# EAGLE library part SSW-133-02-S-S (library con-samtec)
THROUGH-HOLE .025" SQ POST SOCKET Source: Samtec SSW.pdf
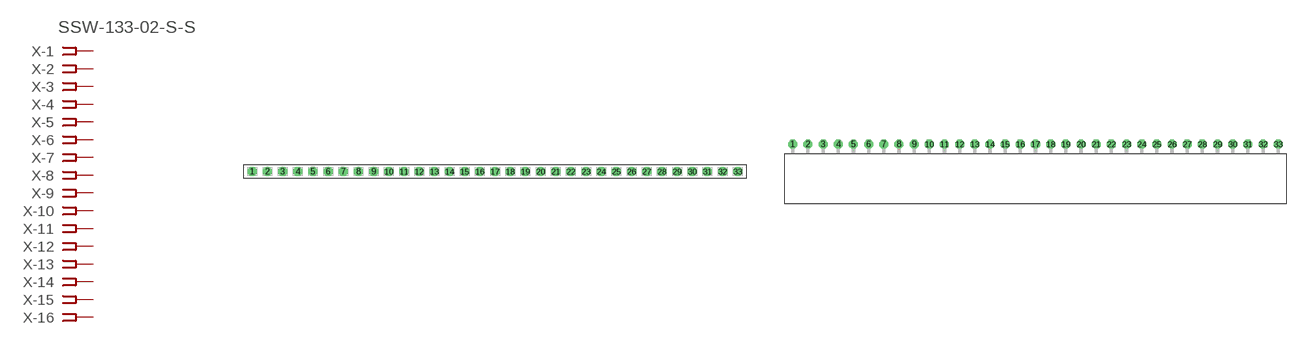
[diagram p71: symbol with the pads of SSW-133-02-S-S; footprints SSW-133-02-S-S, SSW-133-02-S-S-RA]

Designator prefix X; gates -1=FPINV -2=FPIN -3=FPIN -4=FPIN -5=FPIN -6=FPIN -7=FPIN -8=FPIN -9=FPIN -10=FPIN -11=FPIN -12=FPIN -13=FPIN -14=FPIN -15=FPIN -16=FPIN -17=FPIN -18=FPIN -19=FPIN -20=FPIN -21=FPIN -22=FPIN -23=FPIN -24=FPIN -25=FPIN -26=FPIN -27=FPIN -28=FPIN -29=FPIN -30=FPIN -31=FPIN -32=FPIN -33=FPIN

## SSW-133-02-S-S (MPN: SSW-133-02-S-S; OC_FARNELL: unknown; OC_NEWARK: 11P9855)  [SSW-133-02-S-S]
1  -1:1  pas
2  -2:1  pas
3  -3:1  pas
4  -4:1  pas
5  -5:1  pas
6  -6:1  pas
7  -7:1  pas
8  -8:1  pas
9  -9:1  pas
10  -10:1  pas
11  -11:1  pas
12  -12:1  pas
13  -13:1  pas
14  -14:1  pas
15  -15:1  pas
16  -16:1  pas
17  -17:1  pas
18  -18:1  pas
19  -19:1  pas
20  -20:1  pas
21  -21:1  pas
22  -22:1  pas
23  -23:1  pas
24  -24:1  pas
25  -25:1  pas
26  -26:1  pas
27  -27:1  pas
28  -28:1  pas
29  -29:1  pas
30  -30:1  pas
31  -31:1  pas
32  -32:1  pas
33  -33:1  pas

## SSW-133-02-S-S-RA (OC_FARNELL: unknown; OC_NEWARK: unknown)  [SSW-133-02-S-S-RA]
Pads as for SSW-133-02-S-S

## Footprint SSW-133-02-S-S (pad centres in mm)
THROUGH-HOLE .025" SQ POST SOCKET Source: Samtec SSW.pdf
drill 1 pad 1.5 octagon: 1 -40.64,0; 2 -38.1,0; 3 -35.56,0; 4 -33.02,0; 5 -30.48,0; 6 -27.94,0; 7 -25.4,0; 8 -22.86,0; 9 -20.32,0; 10 -17.78,0; 11 -15.24,0; 12 -12.7,0; 13 -10.16,0; 14 -7.62,0; 15 -5.08,0; 16 -2.54,0; 17 0,0; 18 2.54,0; 19 5.08,0; 20 7.62,0; 21 10.16,0; 22 12.7,0; 23 15.24,0; 24 17.78,0; 25 20.32,0; 26 22.86,0; 27 25.4,0; 28 27.94,0; 29 30.48,0; 30 33.02,0; 31 35.56,0; 32 38.1,0; 33 40.64,0

## Footprint SSW-133-02-S-S-RA (pad centres in mm)
THROUGH-HOLE .025" SQ POST SOCKET Source: Samtec SSW.pdf
drill 1 pad 1.5 octagon: 1 -40.64,1.524; 2 -38.1,1.524; 3 -35.56,1.524; 4 -33.02,1.524; 5 -30.48,1.524; 6 -27.94,1.524; 7 -25.4,1.524; 8 -22.86,1.524; 9 -20.32,1.524; 10 -17.78,1.524; 11 -15.24,1.524; 12 -12.7,1.524; 13 -10.16,1.524; 14 -7.62,1.524; 15 -5.08,1.524; 16 -2.54,1.524; 17 0,1.524; 18 2.54,1.524; 19 5.08,1.524; 20 7.62,1.524; 21 10.16,1.524; 22 12.7,1.524; 23 15.24,1.524; 24 17.78,1.524; 25 20.32,1.524; 26 22.86,1.524; 27 25.4,1.524; 28 27.94,1.524; 29 30.48,1.524; 30 33.02,1.524; 31 35.56,1.524; 32 38.1,1.524; 33 40.64,1.524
